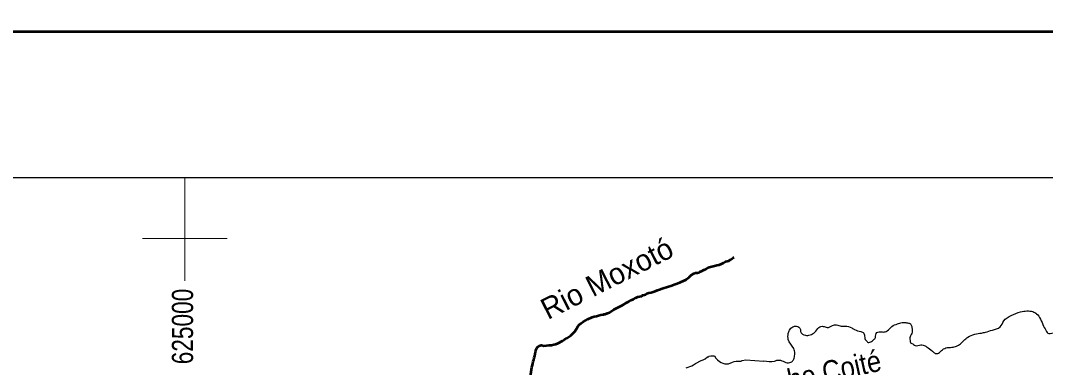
# Model space of a CAD drawing. Extents: x -1643653 to 4543381, y 1624270 to 13878484.
# Drawn here: x 621123 to 645322, y 9021949 to 9030146 of the extents above; entities that cross this region are included whole.
import ezdxf
from ezdxf.enums import TextEntityAlignment as Align

# ---------------------------------------------------------------- set-up
doc = ezdxf.new("R2010")
doc.units = 0
doc.header["$LTSCALE"] = 200
for name, color, linetype, lineweight in [('2', 7, 'Continuous', 13), ('24', 7, 'Continuous', 25), ('3', 7, 'Continuous', 13), ('60', 7, 'Continuous', 13)]:
    doc.layers.add(name, color=color, linetype=linetype, lineweight=lineweight)
doc.layers.add('47', color=7, linetype='Continuous')
doc.layers.add('49', color=7, linetype='Continuous')

msp = doc.modelspace()

# ---------------------------------------------------------------- linework, layer by layer
at = {"layer": '2'}
for p, q in [((625000, 9024000), (625000, 9026438.8)), ((624000, 9025000), (626000, 9025000))]:
    msp.add_line(p, q, dxfattribs=at)
at = {"layer": '24', "lineweight": 53}
msp.add_lwpolyline([(633413.9, 9022478.1), (633421.2, 9022477.1), (633480.4, 9022458.5), (633606.6, 9022474.9), (633658.1, 9022477.9), (633711.2, 9022491.3), (633762.6, 9022500.8), (633814.1, 9022520.8), (633917, 9022578.5), (633968.6, 9022613.4), (634020, 9022642.8), (634070.1, 9022674), (634114.4, 9022705.1), (634164.6, 9022749.5), (634211.6, 9022799.5), (634275.4, 9022905.1), (634276.2, 9022912.6), (634313.5, 9022956), (634360.5, 9022996.6), (634407, 9023028.7), (634463.3, 9023060.8), (634516.2, 9023093.9), (634619.2, 9023138.5), (634669.3, 9023151.8), (634720.7, 9023158.6), (634772.3, 9023177.5), (634823.9, 9023193.7), (634887.8, 9023203.3), (634902.5, 9023207.1), (634926.9, 9023210), (634978.4, 9023232.8), (635028.4, 9023251.7), (635132.8, 9023316), (635288.5, 9023394.6), (635338.7, 9023423), (635440.3, 9023486.3), (635485.1, 9023511.9), (635543.2, 9023541.2), (635595.9, 9023564.9), (635650.6, 9023598), (635699.1, 9023616), (635790.3, 9023636.1), (635793.1, 9023638), (635800.1, 9023649.3), (635819, 9023660.6), (635853.4, 9023668.3), (635876.7, 9023676.8), (635906.5, 9023697.6), (635956.5, 9023710), (636013.3, 9023718.7), (636059.5, 9023732.9), (636105.8, 9023750.9), (636162.5, 9023775.6), (636212.6, 9023793.6), (636275.1, 9023811.7), (636425, 9023859.2), (636478, 9023881.9), (636577.8, 9023919.9), (636690.9, 9023956), (636806.1, 9024008.1), (636823.2, 9024013.8), (636845.9, 9024034.6), (636912.2, 9024085.6), (636934.8, 9024108.2), (636956.3, 9024126.2), (637018.2, 9024171.5), (637057.1, 9024184.8), (637082.8, 9024185.8), (637104.5, 9024187.8), (637134.2, 9024195.4), (637161.3, 9024208.7), (637216.1, 9024229.5), (637230.8, 9024237.1), (637250.3, 9024253.2), (637273.6, 9024257.9), (637295.2, 9024272.1), (637314.4, 9024282.5), (637334, 9024298.6), (637359.5, 9024308.1), (637385.3, 9024320.4), (637537.2, 9024359.4), (637566.8, 9024363.3), (637618.3, 9024376.6), (637671, 9024396.6), (637718.9, 9024421.2), (637745.8, 9024437.2), (637770.3, 9024449.6), (637846.7, 9024469.6), (637851.3, 9024475.2), (637892.7, 9024501.7), (637913.2, 9024518.7), (637958, 9024544.2), (637971.9, 9024555.7)], dxfattribs=at)
at = {"layer": '24'}
msp.add_lwpolyline([(636838.7, 9021941.8), (636972.2, 9021990.2), (637015.9, 9022012), (637062.3, 9022041.3), (637193.3, 9022116), (637241.1, 9022134), (637284.8, 9022155.8), (637346, 9022200.2), (637368.3, 9022205), (637375.3, 9022213.5), (637379.5, 9022215.4), (637419.9, 9022224), (637504.2, 9022227.1), (637543.1, 9022171.7), (637575.9, 9022133.2), (637622.8, 9022093), (637661.8, 9022064.9), (637705.5, 9022049), (637750.8, 9022037), (637835.6, 9022037.2), (637934, 9022078.9), (637976.1, 9022088.5), (638019.7, 9022095.2), (638067.9, 9022095.4), (638139.8, 9022101.2), (638145.1, 9022104.1), (638157.6, 9022114.5), (638245.3, 9022132.2), (638672.6, 9022102.2)], dxfattribs=at)
msp.add_spline([(638666.8, 9022105.1), (638926.3, 9022102.2), (638999.8, 9022122.2), (639130, 9022095.5), (639190.1, 9022065.4), (639313.6, 9022075.5), (639347, 9022095.5), (639387.1, 9022169), (639403.7, 9022285.9), (639377, 9022396.2), (639250.2, 9022610), (639250.2, 9022753.6), (639276.9, 9022830.4), (639360.3, 9022907.3), (639440.5, 9022924), (639537.3, 9022850.5), (639540.6, 9022797), (639654.1, 9022710.2), (639764.3, 9022720.2), (639877.8, 9022780.3), (639974.6, 9022897.2), (640074.8, 9022920.6), (640164.9, 9022893.9), (640295.1, 9022944), (640388.6, 9022957.4), (640502.1, 9022924), (640592.2, 9022924), (640749.2, 9022883.9), (640785.9, 9022860.5), (640815.9, 9022843.8), (640962.8, 9022797), (641029.6, 9022760.3), (641042.9, 9022740.2), (641059.6, 9022633.3), (641109.7, 9022563.2), (641136.4, 9022543.1), (641216.5, 9022566.5), (641253.3, 9022593.2), (641266.6, 9022610), (641293.3, 9022630), (641323.4, 9022750.3), (641363.4, 9022787), (641433.5, 9022793.7), (641493.6, 9022787), (641583.8, 9022813.7), (641697.3, 9022920.6), (641827.5, 9022977.4), (641937.7, 9023010.8), (642004.4, 9023010.8), (642084.6, 9022997.5), (642144.6, 9022967.4), (642168, 9022893.9), (642164.7, 9022750.3), (642121.3, 9022650), (642128, 9022589.9), (642134.6, 9022543.1), (642208.1, 9022493), (642248.1, 9022466.3), (642378.3, 9022483), (642481.8, 9022459.6), (642548.6, 9022416.2), (642685.5, 9022306), (642718.9, 9022282.6), (642795.7, 9022289.2), (642892.5, 9022369.4), (643002.6, 9022419.5), (643109.5, 9022426.2), (643223, 9022452.9), (643393.2, 9022586.6), (643486.7, 9022666.7), (643653.6, 9022733.6), (643810.5, 9022763.6), (643904, 9022783.7), (644067.6, 9022833.8), (644254.6, 9022910.6), (644338, 9023047.6), (644511.6, 9023177.9), (644735.3, 9023264.7), (644882.2, 9023284.8), (645025.8, 9023268.1), (645112.6, 9023218), (645202.7, 9023094.3), (645276.1, 9022927.3), (645349.6, 9022797), (645376.3, 9022760.3), (645506.5, 9022767), (645686.2, 9022762.3), (645814, 9022826.2), (646040.5, 9022896), (646290.2, 9022977.3), (646464.4, 9023111)], degree=3, dxfattribs=at)
at = {"layer": '24', "lineweight": 53}
msp.add_spline([(633213.2, 9021588.7), (633176.5, 9021739.5), (633198.3, 9021957.3), (633285, 9022315.7), (633329, 9022430.2), (633413.9, 9022478.1)], degree=3, dxfattribs=at)
at = {"layer": '3', "lineweight": 53}
msp.add_lwpolyline([(840307.3, 9029887.8), (840307.3, 8886387.8), (560211.7, 8886387.8), (560211.7, 9029887.8)], close=True, dxfattribs=at)
at = {"layer": '3', "lineweight": 25}
msp.add_lwpolyline([(563033.9, 9026438.8), (793061.1, 9026438.8), (793495.6, 8889836.8), (563468.3, 8889836.8)], close=True, dxfattribs=at)
at = {"layer": '60', "lineweight": 25}
msp.add_spline([(814781, 9009175.5), (814787.2, 9009173.4), (814796.9, 9009173.4), (814799.4, 9009172.4), (814805.1, 9009174.5), (814805.6, 9009176.5), (814811.7, 9009179.5), (814811.7, 9009179.5), (814801.5, 9009181), (814790.7, 9009181.5), (814784.1, 9009183.1), (814777.4, 9009185.1), (814778.4, 9009175.5)], degree=3, dxfattribs=at)

# ---------------------------------------------------------------- texts
at = {"layer": '47', "width": 0.8}
msp.add_text('625000', height=500, rotation=90, dxfattribs=at).set_placement((625197.3, 9022917.4), align=Align.CENTER)
at = {"layer": '49'}
msp.add_text('Rio Moxotó', height=500, rotation=26.825, dxfattribs=at).set_placement((635080.7, 9023830.7), align=Align.CENTER)
at = {"layer": '49', "width": 0.9}
msp.add_text('Riacho Coité', height=500, rotation=12.335, dxfattribs=at).set_placement((639799.3, 9021513.7), align=Align.CENTER)

doc.saveas('drawing.dxf')
